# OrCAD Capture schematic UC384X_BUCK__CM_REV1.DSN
size A3; title: UC384x_BUCK_Curent Mode; rev: 2.0
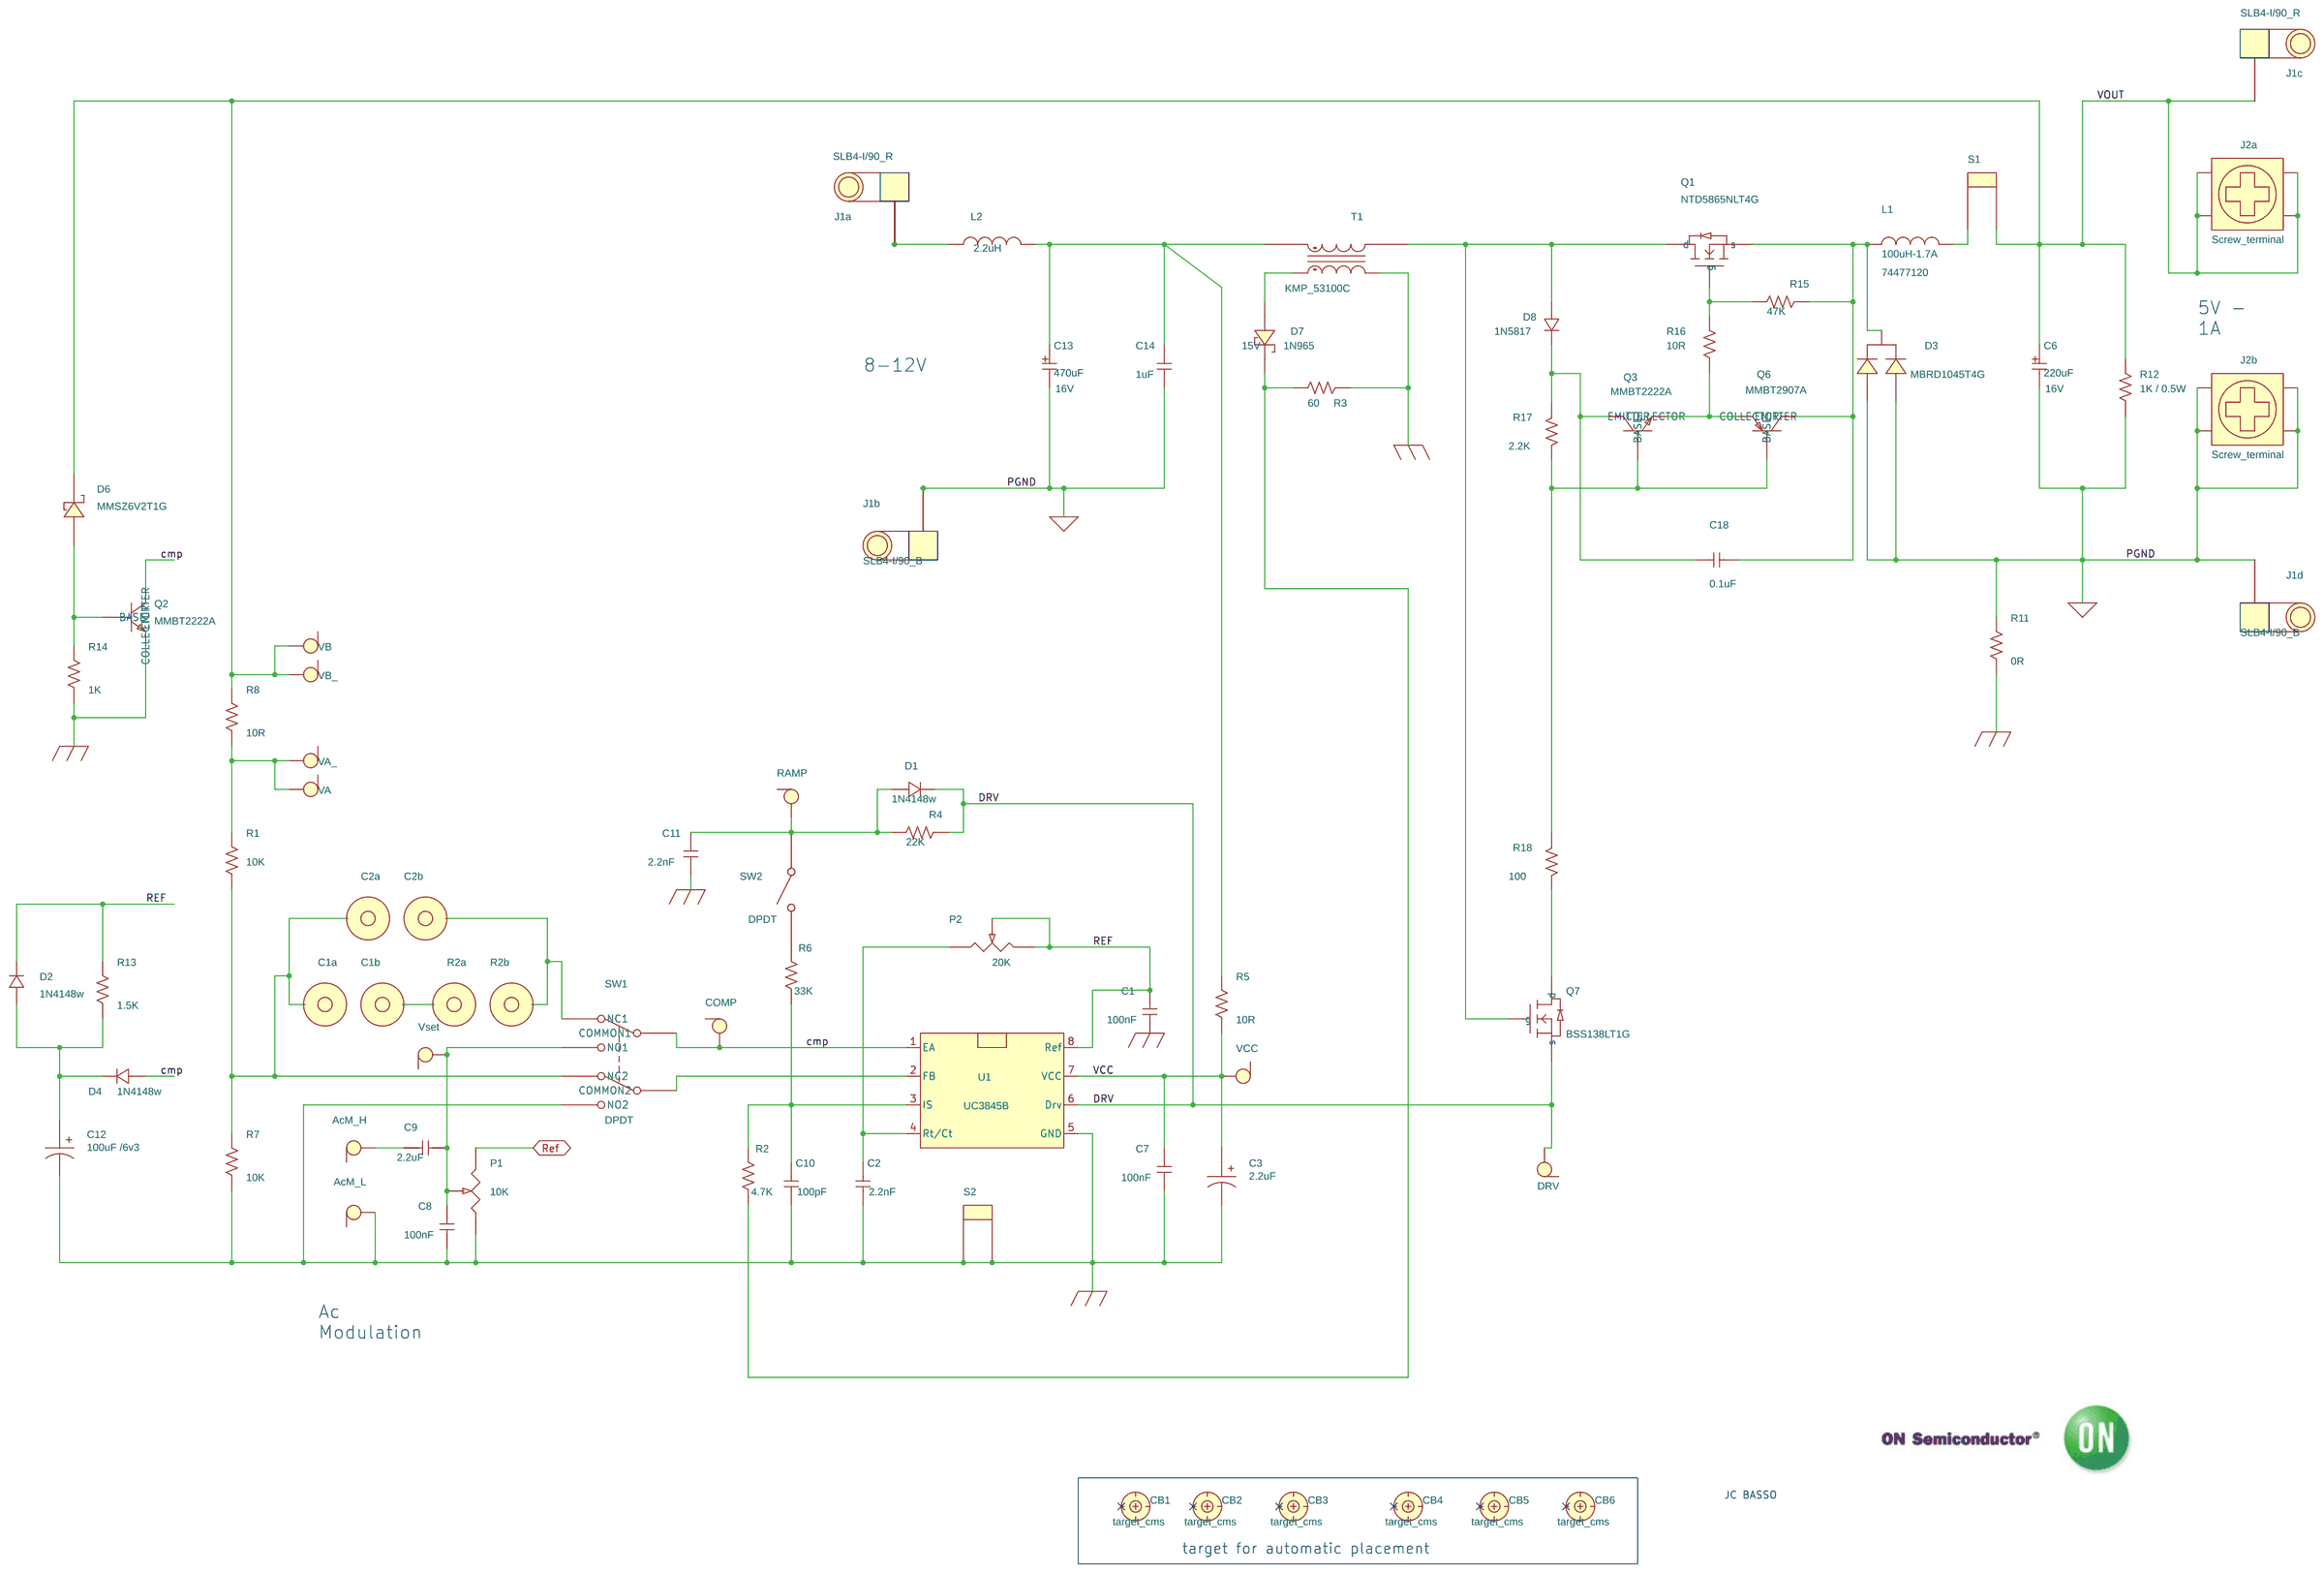
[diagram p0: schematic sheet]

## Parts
AcM_H  TEST POINT  [TP]
AcM_L  TEST POINT  [TP]
C1  100nF  [0805]
C1a  D  [PLOT_5380598-2]
C1b  D  [PLOT_5380598-2]
C2  2.2nF  [0805]
C2a  D  [PLOT_5380598-2]
C2b  D  [PLOT_5380598-2]
C3  2.2uF  [capa_ch_d5_h11_p2]
C6  220uF  [CAPA_ch_D8_H12_P3v5]
C7  100nF  [0805]
C8  100nF  [0805]
C9  2.2uF  [0805]
C10  100pF  [0805]
C11  2.2nF  [0805]
C12  100uF /6v3  [capa_ch_d5_h11_p2]
C13  470uF  [capa_ch_d10_h13_p5]
C14  1uF  [0805]
C18  0.1uF  [0805]
CB1  target_cms  [mire_low]
CB2  target_cms  [mire_low]
CB3  target_cms  [mire_low]
CB4  target_cms  [mire_low]
CB5  target_cms  [mire_low]
CB6  target_cms  [mire_low]
COMP  TEST POINT  [TP]
D1  1N4148w  [SOD123]
D2  1N4148w  [SOD123]
D3  MBRD1045T4G  [DPAK_TO252]
D4  1N4148w  [SOD123]
D6  MMSZ6V2T1G  [SOD123]
D7  1N965  [DO35]
D8  1N5817  [DO41]
DRV  TEST POINT  [TP]
J1a  SLB4-I/90_R  [BANANE_4MM_SLB4]
J1b  SLB4-I/90_B  [BANANE_4MM_SLB4]
J1c  SLB4-I/90_R  [BANANE_4MM_SLB4]
J1d  SLB4-I/90_B  [BANANE_4MM_SLB4]
J2a  Screw_terminal  [pc_7701]
J2b  Screw_terminal  [pc_7701]
L1  100uH-1.7A  [self_WE-PD-1260]
L2  2.2uH  [self_SRN2009]
P1  10K  [potar_12t_3266W]
P2  20K  [potar_12t_3266W]
Q1  NTD5865NLT4G  [DPAK_TO252]
Q2  MMBT2222A  [SOT23]
Q3  MMBT2222A  [SOT23]
Q6  MMBT2907A  [SOT23]
Q7  BSS138LT1G  [SOT23]
R1  10K  [0805]
R2  4.7K  [0805]
R2a  D  [PLOT_5380598-2]
R2b  D  [PLOT_5380598-2]
R3  60  [0805]
R4  22K  [0805]
R5  10R  [0805]
R6  33K  [0805]
R7  10K  [0805]
R8  10R  [0805]
R11  0R  [0805]
R12  1K / 0.5W  [RC21U]
R13  1.5K  [0805]
R14  1K  [0805]
R15  47K  [0805]
R16  10R  [0805]
R17  2.2K  [0805]
R18  100  [0805]
RAMP  TEST POINT  [TP]
S1  Strap  [jumper400h]
S2  Strap  [jumper400h]
SW1  DPDT  [sw_76SD01ST]
SW2  DPDT  [switch-1k2]
T1  KMP_53100C  [murata_5300]
U1  UC3845B  [DIP8_sup]
VA  TEST POINT  [TP]
VA_  TEST POINT  [TP]
VB  TEST POINT  [TP]
VB_  TEST POINT  [TP]
VCC  TEST POINT  [TP]
Vset  TEST POINT  [TP]

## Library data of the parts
AcM_H AcM_L COMP DRV RAMP VA VA_ VB VB_ VCC Vset = TEST_POINT_0_v2
C1 C2 C7-C11 C14 C18 = C: COMPFIXED: NO; COMPGROUP: 0; COMPHEIGHT: 0.000; COMPKEY: NO; COMPLOC: [5662.500,337.500]; COMPLOCKED: NO; COMPROT: 270; COMPSIDE: BOT; DECOUPLER: NO; MEMORY: NO; VOLTAGE: 25V
C1a C1b C2a C2b R2a R2b = T_POINT_R_0
C3 C12 = CAP_POL
C6 = C_elect_0: PART_NUMBER: UPW1E221MPD1TD; Voltage: 16V
C13 = C_elect_0: PART_NUMBER: 860080375014; Voltage: 16V
CB1-CB6 = target_cms
D1 = D1N4148_1: COMPFIXED: NO; COMPGROUP: 0; COMPHEIGHT: 0.000; COMPKEY: NO; COMPLOC: [2825.000,1450.000]; COMPLOCKED: NO; COMPROT: 90; COMPSIDE: TOP; DECOUPLER: NO; FPLIST: DO35 H; MEMORY: NO; PART_NUMBER: 464-198
D2 D4 = D1N4148_2
D3 = dual_diodeAAK
D6 = DIODE_SCHOTTKY_0
D7 = 1N965_0: VOLTAGE: 15V
D8 = 1N5817_0
J1a J1b J1c J1d = HEADER_1_0
J2a J2b = 4_HEADER_0
L1 = CHOKE: PN: 74477120
L2 = L: COMPFIXED: NO; COMPGROUP: 0; COMPHEIGHT: 0.000; COMPKEY: NO; COMPLOC: [6725.000,1075.000]; COMPLOCKED: NO; COMPROT: 270; COMPSIDE: TOP; DECOUPLER: NO; MEMORY: NO; PART_NUMBER: SRN2009T-2R2M
P1 P2 = RESISTOR_VAR
Q1 = NMOS_2: PART_NUMBER: IPA50R250CP
Q2 Q3 = 2N2222A_0
Q6 = 2N2907A_0
Q7 = NMOS_1
R1 R2 R4-R8 R13-R16 = R: COMPFIXED: NO; COMPGROUP: 0; COMPHEIGHT: 0.000; COMPKEY: NO; COMPLOC: [1787.500,750.000]; COMPLOCKED: NO; COMPROT: 90; COMPSIDE: TOP; DECOUPLER: NO; FPLIST: AX/RC05,SM/C_1206H,AX/RC07,AX/RC07_D; MEMORY: NO; VOLTAGE: 200v
R3 R17 R18 = R: COMPFIXED: NO; COMPGROUP: 0; COMPHEIGHT: 0.000; COMPKEY: NO; COMPLOC: [4650.000,400.000]; COMPLOCKED: NO; COMPROT: 180; COMPSIDE: TOP; DECOUPLER: NO; FPLIST: AX/RC07_D,AX/RC07,SM/C_1206H,AX/RC05; MEMORY: NO; PART_NUMBER: LVR03R0800FE12
R11 = R: COMPFIXED: NO; COMPGROUP: 0; COMPHEIGHT: 0.000; COMPKEY: NO; COMPLOC: [1787.500,750.000]; COMPLOCKED: NO; COMPROT: 90; COMPSIDE: TOP; DECOUPLER: NO; FPLIST: AX/RC05,SM/C_1206H,AX/RC07,AX/RC07_D; MEMORY: NO; VOLTAGE: ?v
R12 = R: COMPFIXED: NO; COMPGROUP: 0; COMPHEIGHT: 0.000; COMPKEY: NO; COMPLOC: [1787.500,750.000]; COMPLOCKED: NO; COMPROT: 90; COMPSIDE: TOP; DECOUPLER: NO; FPLIST: AX/RC05,SM/C_1206H,AX/RC07,AX/RC07_D; MEMORY: NO; PART_NUMBER: NC; VOLTAGE: 200v
S1 S2 = TEST_POINT_0
SW1 = SW_DPDT_SM_0
SW2 = SW_SPST: NC: 3
T1 = KMP_0: NC: 2,4,5,6
U1 = UC3845B

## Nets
GND_EARTH: AcM_L.1 C1.2 C2.2 C3.2 C7.2 C8.2 C10.2 C11.2 C12.2 P1.1(A) Q2.2(EMITTER) R3.1 R7.1 R11.1 R14.1 S2.1 S2.2 SW1.2(NO2) T1.3 U1.5(GND)
GND_SIGNAL: C6.2(-) C13.2(-) C14.2 D3.1(A1) D3.3(A2) J1b.1 J1b.2 J1b.3 J1b.4 J1b.5 J1d.1 J1d.2 J1d.3 J1d.4 J1d.5 J2b.1 J2b.2 J2b.3 J2b.4 R11.2 R12.1
VCC: C3.1 C7.1 R5.1 U1.7(VCC) VCC.1
cmp: COMP.1 D4.2 Q2.3(COLLECTOR) SW1.C1(COMMON1) U1.1(EA)
DRV: D1.1 DRV.1 Q7.2(s) R4.1 U1.6(Drv)
Ref: C1.1 D2.1 P1.3(B) P2.2(WIPER) P2.3(B) R13.2 U1.8(Ref)
VOUT: C6.1(+) D6.1(CATHODE) J1c.1 J1c.2 J1c.3 J1c.4 J1c.5 J2a.1 J2a.2 J2a.3 J2a.4 R8.2 R12.2 S1.1 VB.1 VB_.1
N12289703: C13.1(+) C14.1 L2.2 R5.2 T1.8
N12295463: C2.1 P2.1(A) U1.4(Rt/Ct)
N12295845: C10.1 R2.2 R6.1 U1.3(IS)
N12296076: D7.1(CATHODE) R2.1 R3.2
N12296104: SW1.C2(COMMON2) U1.2(FB)
N12296437: C11.1 D1.2 R4.2 RAMP.1 SW2.1
N12297349: R1.2 R8.1 VA.1 VA_.1
N12298127: C1a.1(TP) C2a.1(TP) R1.1 R7.2 SW1.22(NC2)
N12298463: C8.1 C9.2 P1.2(WIPER) SW1.1(NO1) Vset.1
N12299817: C1b.1(TP) R2a.1(TP)
N12299821: C2b.1(TP) R2b.1(TP) SW1.11(NC1)
N12301916: AcM_H.1 C9.1
N12517793: J1a.1 J1a.2 J1a.3 J1a.4 J1a.5 L2.1
N12518756: D8.2 Q1.2(d) Q7.1(g) T1.7
N12518780: Q7.3(d) R18.2
N12519113: D7.2(ANODE) T1.1
N12519598: Q3.1(BASE) Q6.1(BASE) R17.2 R18.1
N12520738: C18.1 D8.1 Q3.3(COLLECTOR) R17.1
N12521657: Q3.2(EMITTER) Q6.2(EMITTER) R16.1
N12521671: Q1.1(g) R15.2 R16.2
N12521759: C18.2 D3.2(C) L1.1 Q1.3(s) Q6.3(COLLECTOR) R15.1
N12522225: L1.2 S1.2
N12524308: C12.1 D2.2 D4.1 R13.1
N12524692: D6.2(ANODE) Q2.1(BASE) R14.2
N12536857: R6.2 SW2.2

Not connected (* = marked no-connect by the designer): CB1 1*; CB2 1*; CB3 1*; CB4 1*; CB5 1*; CB6 1*

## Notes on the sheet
- 5V -
  1A
- 8-12V
- Ac
  Modulation
- JC BASSO
- target for automatic placement
